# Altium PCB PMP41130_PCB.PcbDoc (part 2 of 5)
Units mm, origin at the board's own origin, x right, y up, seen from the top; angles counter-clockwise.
Board outline 74.13 x 200.91 mm, 6 copper layers (Top Layer, Layer 1, Inside Layer 1, Inside Layer 2, Layer 2, Bottom Layer), stack 2.208 mm thick; 356 components, 162 nets, 889 pads, 1511 vias.
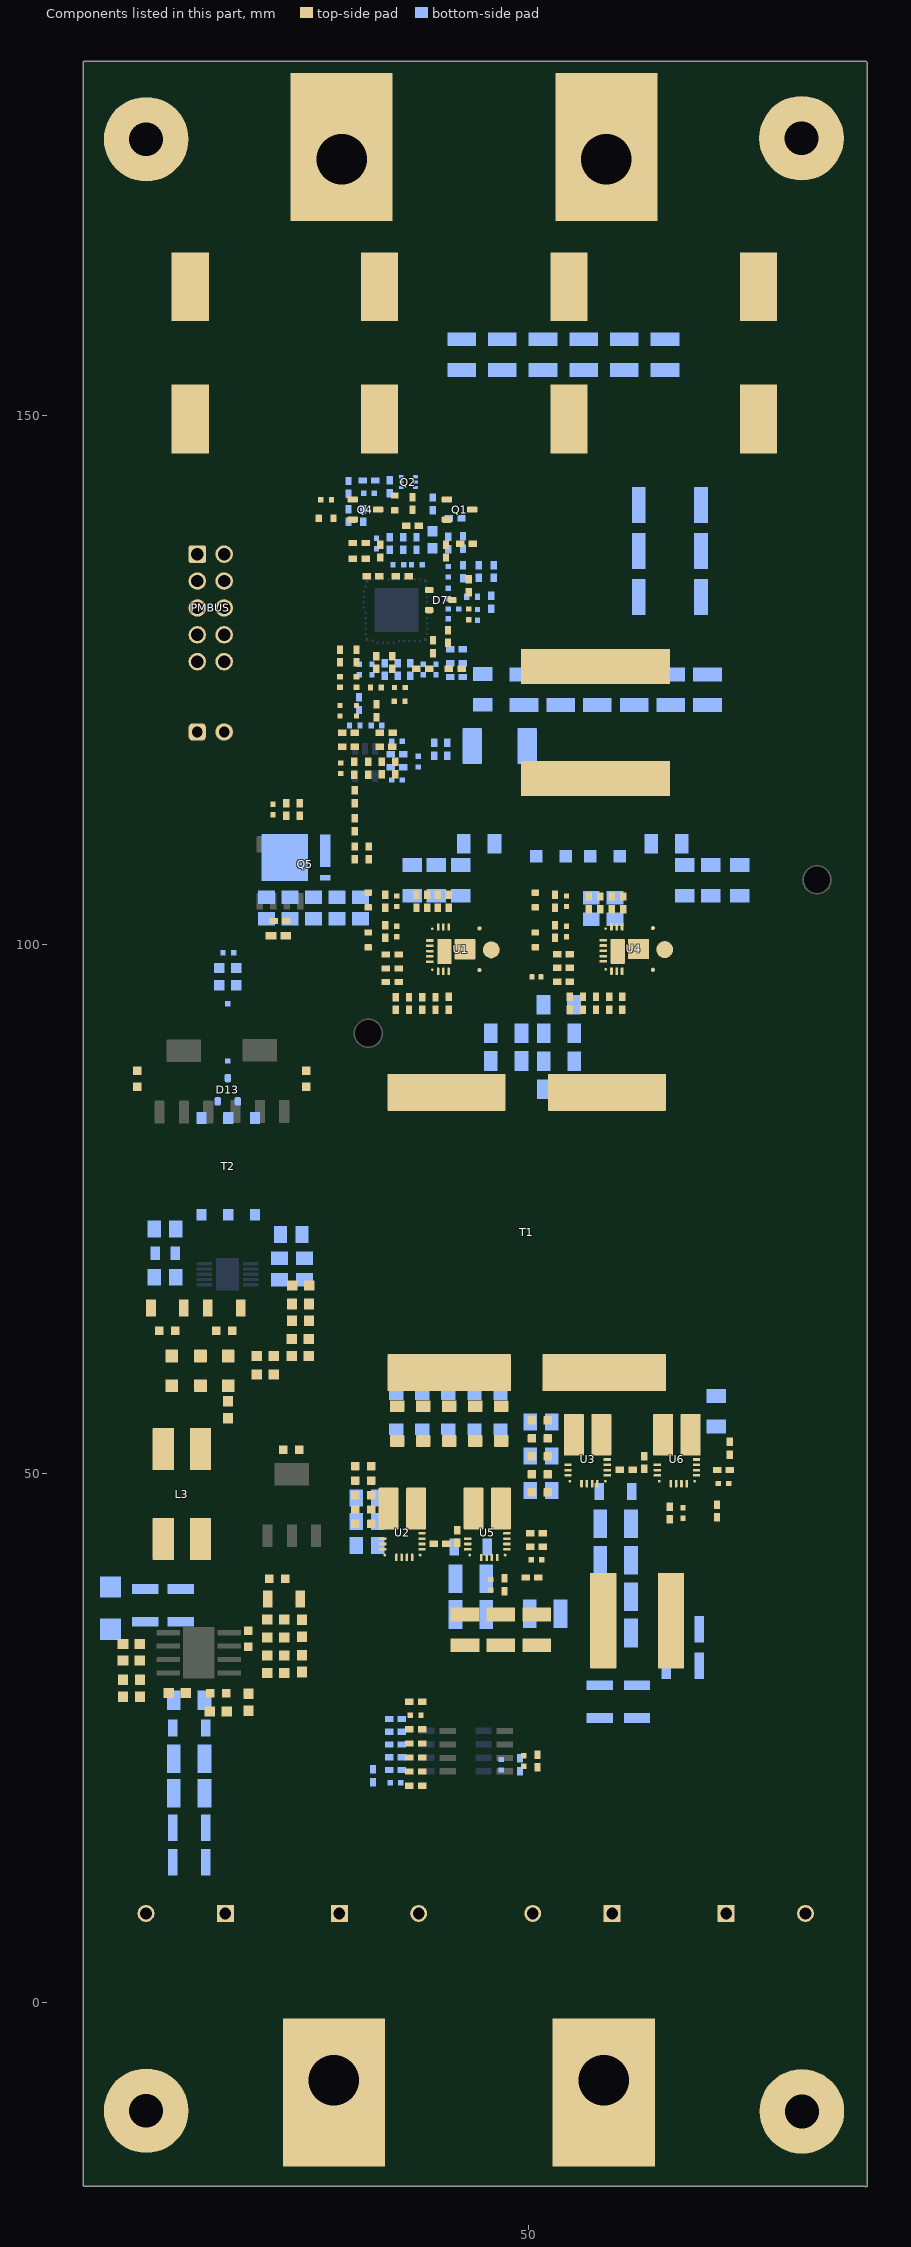
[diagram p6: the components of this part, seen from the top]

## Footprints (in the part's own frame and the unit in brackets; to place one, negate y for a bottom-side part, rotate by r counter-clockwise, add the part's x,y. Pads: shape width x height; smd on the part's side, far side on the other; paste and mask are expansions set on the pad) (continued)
TSW-102-07-G-S [mm] "Samtec 100mil, 1x2, 230 mil above insulator"
  rrect50% 1.65x1.65 hole 1.016: 1(-1.27,0)
  round 1.65 hole 1.016: 2(1.27,0)
  silkscreen extent -3.17,-1.27 2.54,1.27, body extent -2.54,-1.27 2.54,1.27, height 8.38
VBE0015A-MFG [mm]
  round 0.265 smd paste+0 mask-1000: 1(-1.675,2.875) 11(1.675,2.875)
  rrect40% 0.7x0.25 smd paste+0 mask-1000: 2(-1.85,2.325) 3(-1.85,1.825) 4(-1.85,1.325) 5(-1.85,0.825) 8(1.85,1.325) 9(1.85,1.825) 10(1.85,2.325)
  rrect11% 1.9x3.95 smd paste-1000 mask-1000: 6(-1.3,-1.525) 7(1.3,-1.525)
  rrect40% 0.25x0.7 smd paste+0 mask-1000: 12(0.575,3.1) 13(0.075,3.1) 14(-0.425,3.1) 15(-0.925,3.1)
  Top Layer region: -2.15,2.7 -2.169,2.704 -2.185,2.715 -2.196,2.731 -2.2,2.75 -2.2,2.75 -2.2,2.9 -2.193,2.925 -2.175,2.943 -2.15,2.95 -2.15,2.95 -1.85,2.95 -1.812,2.958 -1.779,2.979 -1.758,3.012 -1.75,3.05 -1.75,3.05 -1.75,3.4 -1.746,3.419 -1.735,3.435 -1.719,3.446 -1.7,3.45 -1.7,3.45 -1.55,3.45 -1.531,3.446 -1.515,3.435 -1.504,3.419 -1.5,3.4 -1.5,3.4 -1.5,2.75 -1.504,2.731 -1.515,2.715 -1.531,2.704 -1.55,2.7 -1.55,2.7
  Top Layer region: 2.15,2.7 2.169,2.704 2.185,2.715 2.196,2.731 2.2,2.75 2.2,2.75 2.2,2.9 2.193,2.925 2.175,2.943 2.15,2.95 2.15,2.95 1.85,2.95 1.812,2.958 1.779,2.979 1.758,3.012 1.75,3.05 1.75,3.05 1.75,3.4 1.746,3.419 1.735,3.435 1.719,3.446 1.7,3.45 1.7,3.45 1.55,3.45 1.531,3.446 1.515,3.435 1.504,3.419 1.5,3.4 1.5,3.4 1.5,2.75 1.504,2.731 1.515,2.715 1.531,2.704 1.55,2.7 1.55,2.7
  silkscreen extent -2.93,2.7 -2.68,2.95, body extent -2.35,-3.6 2.35,3.55, height 0.25
VBN0016A-MFG [mm]
  round 0.228 smd paste+0 mask+0: 1(-1.925,3.125) 11(1.925,3.125)
  rrect40% 0.7x0.25 smd paste+0 mask+0: 2(-2.1,2.575) 3(-2.1,2.075) 4(-2.1,1.575) 8(2.1,1.575) 9(2.1,2.075) 10(2.1,2.575)
  round 0.394 smd paste+0 mask+0: 5(-1.969,-1.335) 7(1.969,-1.335)
  rrect8% 2.35x1.33 smd paste-1000 mask+0: 6(-0.225,1.985)
  round 1.603 smd paste-1000 mask+0: 6(-0.059,-2.453)
  rrect5% 1.9x1.976 smd paste-1000 mask+0: 6(0,0.032)
  rrect40% 0.25x0.7 smd paste+0 mask+0: 12(0.825,3.35) 13(0.325,3.35) 14(-0.175,3.35) 15(-0.675,3.35) 16(-1.175,3.35)
  Top Layer region: -2.4,2.95 -2.419,2.954 -2.435,2.965 -2.446,2.981 -2.45,3 -2.45,3 -2.45,3.15 -2.443,3.175 -2.425,3.193 -2.4,3.2 -2.4,3.2 -2.05,3.2 -2.031,3.204 -2.015,3.215 -2.004,3.231 -2,3.25 -2,3.25 -2,3.65 -1.993,3.675 -1.975,3.693 -1.95,3.7 -1.95,3.7 -1.8,3.7 -1.781,3.696 -1.765,3.685 -1.754,3.669 -1.75,3.65 -1.75,3.65 -1.75,3 -1.754,2.981 -1.765,2.965 -1.781,2.954 -1.8,2.95 -1.8,2.95
  Top Layer region: 2.4,2.95 2.419,2.954 2.435,2.965 2.446,2.981 2.45,3 2.45,3 2.45,3.15 2.446,3.169 2.435,3.185 2.419,3.196 2.4,3.2 2.4,3.2 2.05,3.2 2.025,3.207 2.007,3.225 2,3.25 2,3.25 2,3.65 1.996,3.669 1.985,3.685 1.969,3.696 1.95,3.7 1.95,3.7 1.8,3.7 1.781,3.696 1.765,3.685 1.754,3.669 1.75,3.65 1.75,3.65 1.75,3 1.754,2.981 1.765,2.965 1.781,2.954 1.8,2.95 1.8,2.95
  Top Layer region: -0.55,-3.65 -0.554,-3.669 -0.565,-3.685 -0.581,-3.696 -0.6,-3.7 -0.6,-3.7 -0.75,-3.7 -0.775,-3.693 -0.793,-3.675 -0.8,-3.65 -0.8,-3.65 -0.8,-3.425 -0.804,-3.406 -0.815,-3.39 -0.831,-3.379 -0.85,-3.375 -0.85,-3.375 -0.9,-3.375 -0.925,-3.368 -0.943,-3.35 -0.95,-3.325 -0.95,-3.325 -0.95,-1.506 -0.943,-1.481 -0.925,-1.463 -0.9,-1.456 -0.9,-1.456 0.9,-1.456 0.919,-1.46 0.935,-1.471 0.946,-1.487 0.95,-1.506 0.95,-1.506 0.95,-3.325 0.943,-3.35 0.925,-3.368 0.9,-3.375 0.9,-3.375 0.5,-3.375 0.481,-3.379 0.465,-3.39 0.454,-3.406 0.45,-3.425 0.45,-3.425 0.45,-3.65 0.443,-3.675 0.425,-3.693 0.4,-3.7 0.4,-3.7 0.25,-3.7 0.231,-3.696 0.215,-3.685 0.204,-3.669 0.2,-3.65 0.2,-3.65 0.2,-3.425 0.196,-3.406 0.185,-3.39 0.169,-3.379 0.15,-3.375 0.15,-3.375 0,-3.375 -0.019,-3.379 -0.035,-3.39 -0.046,-3.406 -0.05,-3.425 -0.05,-3.425 -0.05,-3.65 -0.054,-3.669 -0.065,-3.685 -0.081,-3.696 -0.1,-3.7 -0.1,-3.7 -0.25,-3.7 -0.275,-3.693 -0.293,-3.675 -0.3,-3.65 -0.3,-3.65 -0.3,-3.425 -0.304,-3.406 -0.315,-3.39 -0.331,-3.379 -0.35,-3.375 -0.35,-3.375 -0.5,-3.375 -0.519,-3.379 -0.535,-3.39 -0.546,-3.406 -0.55,-3.425 -0.55,-3.425
  Top Layer region: -2.075,0.542 -2.1,0.535 -2.118,0.517 -2.125,0.492 -2.125,0.492 -2.125,0.338 -2.129,0.319 -2.14,0.303 -2.156,0.292 -2.175,0.288 -2.175,0.288 -2.4,0.288 -2.425,0.281 -2.443,0.263 -2.45,0.238 -2.45,0.238 -2.45,0.088 -2.443,0.063 -2.425,0.045 -2.4,0.038 -2.4,0.038 -2.175,0.038 -2.15,0.031 -2.132,0.013 -2.125,-0.012 -2.125,-0.012 -2.125,-0.162 -2.132,-0.187 -2.15,-0.205 -2.175,-0.212 -2.175,-0.212 -2.4,-0.212 -2.419,-0.216 -2.435,-0.227 -2.446,-0.243 -2.45,-0.262 -2.45,-0.262 -2.45,-0.412 -2.443,-0.437 -2.425,-0.455 -2.4,-0.462 -2.4,-0.462 -2.175,-0.462 -2.156,-0.466 -2.14,-0.477 -2.129,-0.493 -2.125,-0.512 -2.125,-0.512 -2.125,-0.662 -2.129,-0.681 -2.14,-0.697 -2.156,-0.708 -2.175,-0.712 -2.175,-0.712 -2.4,-0.712 -2.419,-0.716 -2.435,-0.727 -2.446,-0.743 -2.45,-0.762 -2.45,-0.762 -2.45,-0.912 -2.443,-0.937 -2.425,-0.955 -2.4,-0.962 -2.4,-0.962 -2.175,-0.962 -2.156,-0.966 -2.14,-0.977 -2.129,-0.993 -2.125,-1.012 -2.125,-1.012 -2.125,-1.162 -2.129,-1.181 -2.14,-1.197 -2.156,-1.208 -2.175,-1.212 -2.175,-1.212 -2.4,-1.212 -2.419,-1.216 -2.435,-1.227 -2.446,-1.243 -2.45,-1.262 -2.45,-1.262 -2.45,-1.412 -2.443,-1.437 -2.425,-1.455 -2.4,-1.462 -2.4,-1.462 -2.175,-1.462 -2.156,-1.466 -2.14,-1.477 -2.129,-1.493 -2.125,-1.512 -2.125,-1.512 -2.125,-1.662 -2.129,-1.681 -2.14,-1.697 -2.156,-1.708 -2.175,-1.712 -2.175,-1.712 -2.4,-1.712 -2.419,-1.716 -2.435,-1.727 -2.446,-1.743 -2.45,-1.762 -2.45,-1.762 -2.45,-1.912 -2.443,-1.937 -2.425,-1.955 -2.4,-1.962 -2.4,-1.962 -2.175,-1.962 -2.156,-1.966 -2.14,-1.977 -2.129,-1.993 -2.125,-2.012 -2.125,-2.012 -2.125,-2.162 -2.129,-2.181 -2.14,-2.197 -2.156,-2.208 -2.175,-2.212 -2.175,-2.212 -2.4,-2.212 -2.419,-2.216 -2.435,-2.227 -2.446,-2.243 -2.45,-2.262 -2.45,-2.262 -2.45,-2.412 -2.443,-2.437 -2.425,-2.455 -2.4,-2.462 -2.4,-2.462 -2.175,-2.462 -2.156,-2.466 -2.14,-2.477 -2.129,-2.493 -2.125,-2.512 -2.125,-2.512 -2.125,-2.662 -2.129,-2.681 -2.14,-2.697 -2.156,-2.708 -2.175,-2.712 -2.175,-2.712 -2.4,-2.712 -2.419,-2.716 -2.435,-2.727 -2.446,-2.743 -2.45,-2.762 -2.45,-2.762 -2.45,-2.912 -2.443,-2.937 -2.425,-2.955 -2.4,-2.962 -2.4,-2.962 -2.175,-2.962 -2.156,-2.966 -2.14,-2.977 -2.129,-2.993 -2.125,-3.012 -2.125,-3.012 -2.125,-3.166 -2.118,-3.191 -2.1,-3.209 -2.075,-3.216 -2.075,-3.216 -1.8,-3.216 -1.781,-3.212 -1.765,-3.201 -1.754,-3.185 -1.75,-3.166 -1.75,-3.166 -1.75,0.492 -1.754,0.511 -1.765,0.527 -1.781,0.538 -1.8,0.542 -1.8,0.542
  Top Layer region: 2.075,0.542 2.094,0.538 2.11,0.527 2.121,0.511 2.125,0.492 2.125,0.492 2.125,0.338 2.129,0.319 2.14,0.303 2.156,0.292 2.175,0.288 2.175,0.288 2.4,0.288 2.419,0.284 2.435,0.273 2.446,0.257 2.45,0.238 2.45,0.238 2.45,0.088 2.443,0.063 2.425,0.045 2.4,0.038 2.4,0.038 2.175,0.038 2.156,0.034 2.14,0.023 2.129,0.007 2.125,-0.012 2.125,-0.012 2.125,-0.162 2.132,-0.187 2.15,-0.205 2.175,-0.212 2.175,-0.212 2.4,-0.212 2.425,-0.219 2.443,-0.237 2.45,-0.262 2.45,-0.262 2.45,-0.412 2.446,-0.431 2.435,-0.447 2.419,-0.458 2.4,-0.462 2.4,-0.462 2.175,-0.462 2.156,-0.466 2.14,-0.477 2.129,-0.493 2.125,-0.512 2.125,-0.512 2.125,-0.662 2.129,-0.681 2.14,-0.697 2.156,-0.708 2.175,-0.712 2.175,-0.712 2.4,-0.712 2.419,-0.716 2.435,-0.727 2.446,-0.743 2.45,-0.762 2.45,-0.762 2.45,-0.912 2.446,-0.931 2.435,-0.947 2.419,-0.958 2.4,-0.962 2.4,-0.962 2.175,-0.962 2.156,-0.966 2.14,-0.977 2.129,-0.993 2.125,-1.012 2.125,-1.012 2.125,-1.162 2.129,-1.181 2.14,-1.197 2.156,-1.208 2.175,-1.212 2.175,-1.212 2.4,-1.212 2.419,-1.216 2.435,-1.227 2.446,-1.243 2.45,-1.262 2.45,-1.262 2.45,-1.412 2.446,-1.431 2.435,-1.447 2.419,-1.458 2.4,-1.462 2.4,-1.462 2.175,-1.462 2.156,-1.466 2.14,-1.477 2.129,-1.493 2.125,-1.512 2.125,-1.512 2.125,-1.662 2.129,-1.681 2.14,-1.697 2.156,-1.708 2.175,-1.712 2.175,-1.712 2.4,-1.712 2.419,-1.716 2.435,-1.727 2.446,-1.743 2.45,-1.762 2.45,-1.762 2.45,-1.912 2.446,-1.931 2.435,-1.947 2.419,-1.958 2.4,-1.962 2.4,-1.962 2.175,-1.962 2.156,-1.966 2.14,-1.977 2.129,-1.993 2.125,-2.012 2.125,-2.012 2.125,-2.162 2.129,-2.181 2.14,-2.197 2.156,-2.208 2.175,-2.212 2.175,-2.212 2.4,-2.212 2.419,-2.216 2.435,-2.227 2.446,-2.243 2.45,-2.262 2.45,-2.262 2.45,-2.412 2.446,-2.431 2.435,-2.447 2.419,-2.458 2.4,-2.462 2.4,-2.462 2.175,-2.462 2.156,-2.466 2.14,-2.477 2.129,-2.493 2.125,-2.512 2.125,-2.512 2.125,-2.662 2.129,-2.681 2.14,-2.697 2.156,-2.708 2.175,-2.712 2.175,-2.712 2.4,-2.712 2.419,-2.716 2.435,-2.727 2.446,-2.743 2.45,-2.762 2.45,-2.762 2.45,-2.912 2.446,-2.931 2.435,-2.947 2.419,-2.958 2.4,-2.962 2.4,-2.962 2.175,-2.962 2.156,-2.966 2.14,-2.977 2.129,-2.993 2.125,-3.012 2.125,-3.012 2.125,-3.166 2.121,-3.185 2.11,-3.201 2.094,-3.212 2.075,-3.216 2.075,-3.216 1.8,-3.216 1.775,-3.209 1.757,-3.191 1.75,-3.166 1.75,-3.166 1.75,0.492 1.754,0.511 1.765,0.527 1.781,0.538 1.8,0.542 1.8,0.542
  silkscreen extent -3.12,-3.88 2.63,3.88, body extent -2.55,-3.8 2.55,3.8, height 0.25
WCAP-ASLI_D16H17 [mm] "Aluminium Electrolytic V-Chip SMT Capacitors, 16x17mm"
  rect 6.5x3.5 smd: 1(6.25,0) 2(-6.25,0)
  silkscreen extent -8.65,-8.65 8.65,8.65, body extent -9.15,-8.5 9.15,8.5, height 17
WCAP-CSGP_0402_L1W0.5H0.5 [mm] "Ceramic Capacitors, body 1x0.5mm"
  rect 0.5x0.5 smd: 1(-0.5,0) 2(0.5,0)
  body extent -0.5,-0.25 0.5,0.25, height 0.5
WCAP-CSGP_0603_L1.6W0.8H0.8_Reflow [mm] "Ceramic Capacitors, body 1.6x0.8mm"
  rect 0.8x0.8 smd: 1(-0.75,0) 2(0.75,0)
  body extent -0.8,-0.4 0.8,0.4, height 0.8
WCAP-CSGP_0805_L2W1.25H1.25 [mm] "Ceramic Capacitors, body 2x1.25mm"
  rect 0.9x1.3 smd: 1(-0.95,0) 2(0.95,0)
  body extent -1,-0.63 1,0.63, height 1.25
WCAP-CSGP_1206_L3.2W1.6H1.6 [mm] "Ceramic Capacitors, body 3.2x1.6mm"
  rect 0.9x1.6 smd: 1(-1.55,0) 2(1.55,0)
  silkscreen extent -0.8,-0.95 0.8,0.95, body extent -1.6,-0.8 1.6,0.8, height 1.6
WCAP-CSGP_1206_L3.2W1.6H1.25 [mm] "Ceramic Capacitors, body 3.2x1.6mm"
  rect 0.9x1.6 smd: 1(-1.55,0) 2(1.55,0)
  silkscreen extent -0.8,-0.87 0.8,0.87, body extent -1.6,-0.8 1.6,0.8, height 1.25
WCAP-CSGP_1210_L3.2W2.5H2.5 [mm] "Ceramic Capacitors, body 3.2x2.5mm"
  rect 0.9x2.5 smd: 1(-1.55,0) 2(1.55,0)
  silkscreen extent -0.8,-1.4 0.8,1.4, body extent -1.6,-1.25 1.6,1.25, height 2.5
WCAP-CSRF_0402_L1W0.5H0.5 [mm] "Radio Frequency MLCC, body 1x0.5mm"
  rect 0.5x0.5 smd: 1(-0.5,0) 2(0.5,0)
  body extent -0.5,-0.25 0.5,0.25, height 0.5
WE-CBF_0402_L1W0.5H0.5_HS/WB [mm] "SMD EMI Suppression Ferrite  Bead, body 1.00x0.50mm"
  rect 0.5x0.6 smd: 1(-0.5,0) 2(0.5,0)
  body extent -0.5,-0.25 0.5,0.25, height 0.5
WE-TPC-LH [mm] "Wurth Elektronik recommended land pattern, 2009-01-15"
  rect 0.5x0.5 smd: 1(-2.7,0) 2(2.7,0)
  Top Layer region: 0.95,3.15 0.95,3.15 0.95,1.987 1.228,1.838 1.563,1.563 1.838,1.228 2.042,0.846 2.168,0.431 2.211,0 2.168,-0.431 2.042,-0.846 1.838,-1.228 1.563,-1.563 1.228,-1.838 0.95,-1.987 0.95,-3.15 3.15,-3.15 3.15,-3.15 3.15,3.15 0.95,3.15
  Top Layer region: -0.95,3.15 -0.95,3.15 -0.95,1.987 -1.228,1.838 -1.563,1.563 -1.838,1.228 -2.042,0.846 -2.168,0.431 -2.211,0 -2.168,-0.431 -2.042,-0.846 -1.838,-1.228 -1.563,-1.563 -1.228,-1.838 -0.95,-1.987 -0.95,-3.15 -3.15,-3.15 -3.15,-3.15 -3.15,3.15 -0.95,3.15
  silkscreen extent -3.4,-3.4 3.4,3.4, body extent -3.05,-3.05 3.05,3.05, height 3
WE-XHMI_1510_L16.4W15.4H10 [mm] "SMT Power Inductor, 2-Leads, body 16.4x15.4mm"
  rect 14.1x3.3 smd: 1(0,5.3) 2(0,-5.3)
  Top Layer keep-out region: -8.2,3.45 8.2,3.45 8.2,-3.45 -8.2,-3.45
  silkscreen extent -8.98,-7.85 8.35,7.85, body extent -8.2,-7.7 8.2,7.7, height 10
WEEE_Minimum [mm] "WEEElie bin"
  silkscreen extent -2.42,-4.38 2.52,2.65
Wurth_750316769 [mm] "SMD, 6-Leads, Body 7.14x6.73mm, Pitch 2.54mm"
  rrect10% 1.12x0.96 smd: 1(-4.57,2.54) 2(-4.57,0) 3(-4.57,-2.54) 4(4.57,-2.54) 5(4.57,0) 6(4.57,2.54)
  silkscreen extent -5,-3.36 3.57,3.36, body extent -5.02,-3.36 5.02,3.36, height 4.19
WURTH_61301021121 [mm] "Header, 2.54mm, 5x2, TH"
  rrect25% 1.65x1.65 hole 1.15: 1(-5.08,-1.27)
  round 1.65 hole 1.15: 2(-5.08,1.27) 3(-2.54,-1.27) 4(-2.54,1.27) 5(0,-1.27) 6(0,1.27) 7(2.54,-1.27) 8(2.54,1.27) 9(5.08,-1.27) 10(5.08,1.27)
  silkscreen extent -6.35,-2.9 6.35,2.54, body extent -6.35,-2.54 6.35,2.54, height 8.54

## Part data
C1 C7 C9 C20 C21 C22 C29 C32 C53 C54: library part CMP-0098402-1, "10 µF ±10% 100V Ceramic Capacitor X6S 1206 (3216 Metric)", Digikey Part Number=445-C3216X6S2A106K160ACCT-ND, Manufacturer=TDK, Mouser Part Number=810-C3216X6S2A106K16, Operating Temperature Range="-55°C to +105°C", TempCo=22%, Temperature Characteristic=X6S, Tolerance_%=10%, ValueDisplayed=10uF
C2 C63 C75 C76: library part CMP-0064928-2, "CAP, CERM, 0.47 uF, 25 V,+/- 10%, X5R, 0402", Cap_Case=0402, Manufacturer=MuRata, Supplier Part Number 1=490-14365-1-ND, TempCo=X5R, Tolerance_%=10%, Value1=Unknown, Value2=25V, ValueDisplayed=0.47uF
C3 C4: library part CMP-0064955-1, "CAP, CERM, 0.1 uF, 250 V,+/- 20%, X7T, 0805", Cap_Case=0805, Manufacturer=TDK, Supplier Part Number 1=445-6808-1-ND, TempCo=X7T, Tolerance_%=20%, Value1=Unknown, Value2=250V, ValueDisplayed=0.1uF
C5 C6: library part CMP-0009054-2, "CAP, CERM, 470 pF, 500 V, +/- 10%, X7R, 1206", Cap_Case=1206, Manufacturer=Vishay-Vitramon, Supplier Part Number 1=720-1029-1-ND, TempCo=X7R, Tolerance_%=10%, Value1=Unknown, Value2=500V, ValueDisplayed=470pF
C8 C74 C100 C147: library part CMP-0078625-1, "CAP, CERM, 1 µF, 25 V,+/- 20%, X5R, 0402", Cap_Case=0402, Manufacturer=MuRata, Supplier Part Number 1=490-10018-1-ND, TempCo=X5R, Tolerance_%=20%, Value2=25V, ValueDisplayed=1µF
C10 C11 C12 C13 C137 C138 C157 C158: library part CMP-0105033-1, "WCAP-CSGP Multilayer Ceramic Chip Capacitor, General Purpose, size 1210, X7R, 2.2µF, 100VDC", Capacitance Tolerance=+/-10%, Case/Size Code=1210, Insulation Resistance=0.05GOhm, Manufacturer="Wurth Elektronik", Operating Temperature Max=125°C, Operating Temperature Min=-55°C, Rated Voltage (DC)=100V
C14 C15 C16 C17 C18 C19 C141 C142 C143 C144 C145: library part CMP-0007891-2, "CAP, CERM, 1 uF, 100 V, +/- 10%, X7S, 0805", Cap_Case=0805, Manufacturer=TDK, Supplier Part Number 1=445-5205-1-ND, TempCo=X7S, Tolerance_%=10%, Value1="0.008255 ohm", Value2=100V, ValueDisplayed=1uF
C23 C24 C25 C26 C27 C28 C37 C38 C39 C40 C41 C42 C43 C45 C47 C48 C57 C58 C59 C60 C155 C156: library part CMP-0009135-2, "CAP, CERM, 4.7 uF, 100 V, +/- 10%, X7S, 1210", Cap_Case=1210, Manufacturer=TDK, Supplier Part Number 1=445-8912-1-ND, TempCo=X7S, Tolerance_%=10%, Value1=Unknown, Value2=100V, ValueDisplayed=4.7uF
C30 C31: library part CMP-0009030-2, "CAP, CERM, 100 pF, 1000 V, +/- 5%, C0G/NP0, 1206", Cap_Case=1206, Manufacturer=Vishay-Vitramon, Supplier Part Number 1=720-1011-1-ND, TempCo=C0G/NP0, Tolerance_%=5%, Value1=Unknown, Value2=1000V, ValueDisplayed=100pF
C33 C34 C35 C36: library part CMP-0009843-2, "CAP, AL, 470 uF, 100 V, +/- 20%, TH", Cap_Case=16x25mm, Manufacturer=Panasonic, Supplier Part Number 1=P5316-ND, Tolerance_%=20%, Value1=Unknown, Value2=100V, ValueDisplayed=470uF
C44 C127 C131: library part CMP-0115410-1, "WCAP-CSGP Multilayer Ceramic Chip Capacitor, General Purpose, size 0603, X7R, 2.2µF, 10VDC", Capacitance Tolerance=+/-10%, Case/Size Code=0603, Insulation Resistance=0.02GOhm, Manufacturer="Wurth Elektronik", Operating Temperature Max=125°C, Operating Temperature Min=-55°C, Rated Voltage (DC)=10V
C46 C128 C135: library part CMP-0108465-1, "WCAP-CSGP Multilayer Ceramic Chip Capacitor, General Purpose, size 1206, X7R, 22µF, 10VDC", Capacitance Tolerance=+/-10%, Case/Size Code=1206, Insulation Resistance=0.005GOhm, Manufacturer="Wurth Elektronik", Operating Temperature Max=125°C, Operating Temperature Min=-55°C, Rated Voltage (DC)=10V
C49 C50 C51 C52: library part CMP-0110669-1, "WCAP-ASLI Aluminum Electrolytic Capacitor, V-Chip, D16 x H17mm, 150uF, 100V", Capacitance Tolerance=+/-20%, Leakage Current=150uA, Manufacturer="Wurth Elektronik", Operating Temperature Max=105°C, Operating Temperature Min=-55°C, Rated Voltage (DC)=100V, Ripple Current=500mA
C55 C56 C99 C121: library part CMP-0081010-1, "CAP, CERM, 2.2 µF, 25 V,+/- 20%, X5R, 0402", Cap_Case=0402, Manufacturer=MuRata, Supplier Part Number 1=490-10457-1-ND, TempCo=X5R, Tolerance_%=20%, Value2=25V, ValueDisplayed=2.2µF
C61 C62: library part CMP-0009275-2, "CAP, CERM, 0.1 uF, 100 V, +/- 10%, X7R, 1210", Cap_Case=1210, Manufacturer=Vishay-Vitramon, Supplier Part Number 1=720-1082-1-ND, TempCo=X7R, Tolerance_%=10%, Value1=Unknown, Value2=100V, ValueDisplayed=0.1uF
C64 C65 C66 C67 C68 C69 C70 C71 C72 C73: library part CMP-0097294-1, "0.1 µF ±10% 100V Ceramic Capacitor X7R 0603 (1608 Metric)", Digikey Part Number=732-885012206120TR-ND, Manufacturer="Wurth Electronics", Mouser Part Number=710-885012206120, Operating Temperature Range="-55°C to +125°C", TempCo=15%, Temperature Characteristic=X7R, Tolerance_%=10%, ValueDisplayed=100nF
C77 C78: library part CMP-0053309-1, "WCAP-CSGP Multilayer Ceramic Chip Capacitor, General Purpose, size 0402, X7R, 100pF, 50VDC", Capacitance Tolerance=+/-10%, Case/Size Code=0402, Insulation Resistance=10GOhm, Manufacturer="Wurth Elektronik", Operating Temperature Max=125°C, Operating Temperature Min=-55°C, Rated Voltage (DC)=50V
C79 C80 C81 C86 C87 C91 C97 C98 C106 C107 C108 C109: library part CMP-0104156-1, "WCAP-CSGP Multilayer Ceramic Chip Capacitor, General Purpose, size 0402, NP0, 33pF, 50VDC", Capacitance Tolerance=+/-5%, Case/Size Code=0402, Insulation Resistance=10GOhm, Manufacturer="Wurth Elektronik", Operating Temperature Max=125°C, Operating Temperature Min=-55°C, Rated Voltage (DC)=50V
C82 C83 C93 C94: library part CMP-0006213-2, "CAP, CERM, 33 pF, 25 V, +/- 5%, C0G/NP0, 0402", Cap_Case=0402, Manufacturer="Wurth Elektronik", Supplier Part Number 1=710-885012005043, TempCo=C0G/NP0, Tolerance_%=5%, Value1=Unknown, Value2=25V, ValueDisplayed=33pF
C84 C85 C95 C96: library part CMP-0052531-1, "WCAP-CSGP Multilayer Ceramic Chip Capacitor, General Purpose, size 0402, X7R, 100nF, 16VDC", Capacitance Tolerance=+/-10%, Case/Size Code=0402, Insulation Resistance=5GOhm, Manufacturer="Wurth Elektronik", Operating Temperature Max=125°C, Operating Temperature Min=-55°C, Rated Voltage (DC)=16V
C88: library part CMP-0119248-1, "WCAP-CSGP Multilayer Ceramic Chip Capacitor, General Purpose, size 0402, X7R, 100nF, 10VDC", Capacitance Tolerance=+/-10%, Case/Size Code=0402, Insulation Resistance=5GOhm, Manufacturer="Wurth Elektronik", Operating Temperature Max=125°C, Operating Temperature Min=-55°C, Rated Voltage (DC)=10V
C89 C111 C119: library part CMP-0107736-1, "WCAP-CSGP Multilayer Ceramic Chip Capacitor, General Purpose, size 0402, NP0, 1nF, 50VDC", Capacitance Tolerance=+/-5%, Case/Size Code=0402, Insulation Resistance=10GOhm, Manufacturer="Wurth Elektronik", Operating Temperature Max=125°C, Operating Temperature Min=-55°C, Rated Voltage (DC)=50V
C90 C101 C103 C105: library part CMP-0119280-1, "WCAP-CSGP Multilayer Ceramic Chip Capacitor, General Purpose, size 0402, X7R, 10nF, 25VDC", Capacitance Tolerance=+/-10%, Case/Size Code=0402, Insulation Resistance=10GOhm, Manufacturer="Wurth Elektronik", Operating Temperature Max=125°C, Operating Temperature Min=-55°C, Rated Voltage (DC)=25V
C92 C113: library part CMP-0116016-1, "WCAP-CSRF Multilayer Ceramic Chip Capacitor, High Frequency, size 0402, NP0 Class I, 22pF, 50VDC", Capacitance Tolerance=+/-5%, Case/Size Code=0402, Insulation Resistance=10GOhm, Manufacturer="Wurth Elektronik", Operating Temperature Max=125°C, Operating Temperature Min=-55°C, Rated Voltage (DC)=50V
C102 C104: library part CMP-0006612-2, "CAP, CERM, 4.7 uF, 25 V, +/- 20%, X5R, 0402", Cap_Case=0402, Manufacturer=MuRata, TempCo=X5R, Tolerance_%=20%, Value1=Unknown, Value2=25V, ValueDisplayed=4.7uF
C110: library part CMP-0006852-4, "CAP, CERM, 0.01 uF, 200 V, +/- 10%, X7R, 0603", Cap_Case=0603, Manufacturer=Kemet, Supplier Part Number 1=399-5088-1-ND, TempCo=X7R, Tolerance_%=10%, Value1=Unknown, Value2=200V, ValueDisplayed=0.01uF
C112: library part CMP-0006684-2, "CAP, CERM, 0.022 uF, 50 V, +/- 10%, X7R, 0402", Cap_Case=0402, Manufacturer=MuRata, Supplier Part Number 1=490-3884-1-ND, TempCo=X7R, Tolerance_%=10%, Value1=Unknown, Value2=50V, ValueDisplayed=0.022uF
C114: library part CMP-0078224-1, "CAP, CERM, 0.01 µF, 50 V,+/- 10%, X8R, AEC-Q200 Grade 0, 0402", Cap_Case=0402, Manufacturer=TDK, Supplier Part Number 1=445-12303-1-ND, TempCo=X8R, Tolerance_%=10%, Value2=50V, ValueDisplayed=0.01µF
C115 C116 C117: library part CMP-0111322-1, "WCAP-CSGP Multilayer Ceramic Chip Capacitor, General Purpose, size 0402, NP0, 10pF, 50VDC", Capacitance Tolerance=+/-5%, Case/Size Code=0402, Insulation Resistance=10GOhm, Manufacturer="Wurth Elektronik", Operating Temperature Max=125°C, Operating Temperature Min=-55°C, Rated Voltage (DC)=50V
C118 C152 C154: library part CMP-0111809-1, "WCAP-CSGP Multilayer Ceramic Chip Capacitor, General Purpose, size 0402, X7R, 100nF, 50VDC", Capacitance Tolerance=+/-5%, Case/Size Code=0402, Insulation Resistance=0.5GOhm, Manufacturer="Wurth Elektronik", Operating Temperature Max=125°C, Operating Temperature Min=-55°C, Rated Voltage (DC)=50V
C120: library part CMP-0119274-1, "WCAP-CSGP Multilayer Ceramic Chip Capacitor, General Purpose, size 0402, X7R, 1nF, 25VDC", Capacitance Tolerance=+/-10%, Case/Size Code=0402, Insulation Resistance=10GOhm, Manufacturer="Wurth Elektronik", Operating Temperature Max=125°C, Operating Temperature Min=-55°C, Rated Voltage (DC)=25V
C122: library part CMP-0053546-1, "WCAP-CSGP Multilayer Ceramic Chip Capacitor, General Purpose, size 0402, X7R, 1.5nF, 50VDC", Capacitance Tolerance=+/-10%, Case/Size Code=0402, Insulation Resistance=10GOhm, Manufacturer="Wurth Elektronik", Operating Temperature Max=125°C, Operating Temperature Min=-55°C, Rated Voltage (DC)=50V
C123 C124 C160: library part CMP-0119652-1, "WCAP-CSGP Multilayer Ceramic Chip Capacitor, General Purpose, size 1206, X7R, 100nF, 100VDC", Capacitance Tolerance=+/-10%, Case/Size Code=1206, Insulation Resistance=1GOhm, Manufacturer="Wurth Elektronik", Operating Temperature Max=125°C, Operating Temperature Min=-55°C, Rated Voltage (DC)=100V
C125: library part CMP-0009043-2, "CAP, CERM, 0.01 uF, 1000 V, +/- 10%, X7R, 1206", Cap_Case=1206, Manufacturer=Vishay-Vitramon, Supplier Part Number 1=720-1022-1-ND, TempCo=X7R, Tolerance_%=10%, Value1=Unknown, Value2=1000V, ValueDisplayed=0.01uF
C126 C129 C136: library part CMP-0115435-1, "WCAP-CSGP Multilayer Ceramic Chip Capacitor, General Purpose, size 0603, X7R, 1µF, 16VDC", Capacitance Tolerance=+/-10%, Case/Size Code=0603, Insulation Resistance=0.1GOhm, Manufacturer="Wurth Elektronik", Operating Temperature Max=125°C, Operating Temperature Min=-55°C, Rated Voltage (DC)=16V
C130 C134: library part CMP-0111894-1, "WCAP-CSGP Multilayer Ceramic Chip Capacitor, General Purpose, size 0603, X7R, 2.2nF, 50VDC", Capacitance Tolerance=+/-10%, Case/Size Code=0603, Insulation Resistance=10GOhm, Manufacturer="Wurth Elektronik", Operating Temperature Max=125°C, Operating Temperature Min=-55°C, Rated Voltage (DC)=50V
C132: library part CMP-0006901-4, "CAP, CERM, 0.022 uF, 50 V, +/- 10%, X7R, 0603", Cap_Case=0603, Manufacturer=Kemet, Supplier Part Number 1=399-1280-1-ND, TempCo=X7R, Tolerance_%=10%, Value1=Unknown, Value2=50V, ValueDisplayed=0.022uF
C133: library part CMP-0081011-1, "CAP, CERM, 0.1 µF, 100 V,+/- 10%, X7R, AEC-Q200 Grade 1, 0603", Cap_Case=0603, Manufacturer="Taiyo Yuden", Supplier Part Number 1=587-6009-1-ND, TempCo=X7R, Tolerance_%=10%, Value2=100V, ValueDisplayed=0.1µF
C139: library part CMP-0006842-4, "CAP, CERM, 1000 pF, 50 V, +/- 5%, C0G/NP0, 0603", Cap_Case=0603, Manufacturer=Kemet, Supplier Part Number 1=317202, TempCo=C0G/NP0, Tolerance_%=5%, Value1=Unknown, Value2=50V, ValueDisplayed=1000pF
C140: library part CMP-0075366-3, "CAP, CERM, 2.2 µF, 25 V,+/- 10%, X7S, 0603", Cap_Case=0603, Manufacturer=MuRata, Supplier Part Number 1=490-12732-1-ND, TempCo=X7S, Tolerance_%=10%, Value2=25V, ValueDisplayed=2.2µF
C146: library part CMP-0006253-2, "CAP, CERM, 1 uF, 35 V, +/- 10%, JB, 0402", Cap_Case=0402, Manufacturer=TDK, Supplier Part Number 1=445-11014-1-ND, TempCo=JB, Tolerance_%=10%, Value1=Unknown, Value2=35V, ValueDisplayed=1uF
C148: library part CMP-0008303-3, "CAP, CERM, 10 uF, 25 V, +/- 20%, X5R, 0805", Cap_Case=0805, Manufacturer=MuRata, TempCo=X5R, Tolerance_%=20%, Value1=Unknown, Value2=25V, ValueDisplayed=10uF
C149: library part CMP-0008335-2, "CAP, CERM, 0.1 uF, 25 V, +/- 10%, X7R, 0805", Cap_Case=0805, Manufacturer=MuRata, Supplier Part Number 1=490-1673-1-ND, TempCo=X7R, Tolerance_%=10%, Value1=Unknown, Value2=25V, ValueDisplayed=0.1uF
C150 C151: library part CMP-0007357-5, "CAP, CERM, 4.7 uF, 35 V, +/- 10%, X5R, 0603", Cap_Case=0603, Manufacturer=MuRata, Supplier Part Number 1=490-7205-1-ND, TempCo=X5R, Tolerance_%=10%, Value1=Unknown, Value2=35V, ValueDisplayed=4.7uF
C153: library part CMP-0114900-1, "WCAP-CSGP Multilayer Ceramic Chip Capacitor, General Purpose, size 0402, NP0, 47pF, 50VDC", Capacitance Tolerance=+/-5%, Case/Size Code=0402, Insulation Resistance=10GOhm, Manufacturer="Wurth Elektronik", Operating Temperature Max=125°C, Operating Temperature Min=-55°C, Rated Voltage (DC)=50V
C159: library part CMP-0008711-2, "CAP, CERM, 1 uF, 100 V, +/- 20%, X7R, 1206", Cap_Case=1206, Manufacturer=TDK, Supplier Part Number 1=445-4468-1-ND, TempCo=X7R, Tolerance_%=20%, Value1=Unknown, Value2=100V, ValueDisplayed=1uF
Css1: library part CMP-0111941-1, "WCAP-CSGP Multilayer Ceramic Chip Capacitor, General Purpose, size 0805, X7R, 680nF, 10VDC", Capacitance Tolerance=+/-10%, Case/Size Code=0805, Insulation Resistance=0.7GOhm, Manufacturer="Wurth Elektronik", Operating Temperature Max=125°C, Operating Temperature Min=-55°C, Rated Voltage (DC)=10V
D1 D2 D9 D10 D12: library part CMP-0122261-1, "Diode 200 V 2A Surface Mount SOD-123W", Digikey Part Number=1727-7417-1-ND, Forward Current=2A, Manufacturer=Nexperia, Max Surge Forward Current=50A, Mouser Part Number=771-PNE20020ERX, Operating Temperature Range="to +175°C", Peak Reverse Current=0.01uA, ValueDisplayed=17pF
D3 D4 D5 D6 D8 D14: library part CMP-0122254-1, "Diode Schottky 40V 0.25A 2-Pin SOD-523 T/R", Digikey Part Number=SDM20U40-7DICT-ND, Forward Current=250mA, Manufacturer="Diodes Inc.", Max Surge Forward Current=1A, Mouser Part Number=621-SDM20U40, Operating Temperature Range="-65°C to +125°C", Peak Reverse Current=5uA, ValueDisplayed=50pF
D7: library part CMP-0076925-2, "Diode, Switching, 100 V, 0.215 A, SOT-23", Manufacturer=Nexperia, Value1=0.215A, Value2=1.25V
D11: library part CMP-0122570-1, "Diode TVS Single Uni-Dir 70V 400W Automotive 2-Pin SMA T/R", Breakdown Voltage=77.8V, Clamping Voltage=113V, Digikey Part Number=1SMA70AT3GOSCT-ND, Manufacturer=Littelfuse, Mouser Part Number=863-1SMA70AT3G, Operating Temperature Range="-65°C to +150°C", ValueDisplayed=190pF
D13: library part CMP-0077061-2, "Diode, Switching, 70 V, 0.25 A, AEC-Q101, SOT-23", Manufacturer=Vishay-Semiconductor, Value1=0.25A, Value2=1.25V
FB1 FB2 FB3 FB4 FB5 FB6: library part CMP-0066373-1, "WE-CBF SMT EMI Suppression Ferrite Bead, size 0402, 470Ohm, 0.62A", Case/Size Code=0402, DC Resistance Max=0.45Ohm, Manufacturer="Wurth Elektronik", Operating Temperature Max=125°C, Operating Temperature Min=-55°C, Rated Current=0.62A
H1 H2 H3 H4: library part CMP-0003617-1, "Machine Screw, Round, #4-40 x 1/4, Nylon, Philips panhead", Manufacturer="B&F Fastener Supply", Supplier Part Number 1=H542-ND
H5 H6 H7 H8: library part CMP-0003610-1, "Standoff, Hex, 0.5\"L #4-40 Nylon", Manufacturer=Keystone, Supplier Part Number 1=36-1902C-ND
J1: library part CMP-0075405-3, "Header, 100mil, 2x1, Gold, TH", Color=Black, Current_A=6.3A, Manufacturer=Samtec, Supplier Part Number 1=SAM1029-02-ND, Voltage_V=550V
L1: library part CMP-0124159-1, "1 µH Shielded Molded Inductor 48.2 A 1.61mOhm Max Nonstandard", Digikey Part Number=732-74439369010CT-ND, Manufacturer=Wurth, Mouser Part Number=710-74439369010, Operating Temperature Range="-40°C to +125°C", Self Resonant Frequency=40MHz, Test Frequency=100kHz, Tolerance_%=20%
L2: library part CMP-0099219-1, "WE-XHMI SMT Power Inductor, size 1510, 6.8uH, 15A, 4.1mOhm", Case/Size Code=1510, DC Resistance=4.1mOhm, Inductance=6.8uH, Manufacturer="Wurth Elektronik", Operating Temperature Max=125°C, Operating Temperature Min=-40°C, Performance Rated Current=25.3A, Rated Current=15A, Saturation Current=40.05A, Self Resonant Frequency=14MHz
L3: library part CMP-0122580-1, "Shielded Coupled Inductor 150uH 10% 100kHz 0.465Ohm 1.1A 12.3x12.3x6.2mm SMT AECQ200", Manufacturer=Coilcraft, Operating Temperature Range=to, Self Resonant Frequency=5.4MHz, Test Frequency=100kHz, Tolerance_%=10%
L4: library part CMP-0064419-2, "Inductor, Shielded Drum Core, Ferrite, 12 uH, 1.25 A, 0.06 ohm, SMD", Manufacturer="Wurth Elektronik", Supplier Part Number 1=732-1044-1-ND, Value1="0.06 ohm", Value2=1.25A, ValueDisplayed=12uH
Logo1: library part CMP-0074844-1
Logo2: library part CMP-0074838-1, "Texas Instrument Corporate Signature"
Logo3: library part CMP-0074847-1, "FCC_disclaimer"
Logo4: library part CMP-0074769-1
PMBUS: library part CMP-0054806-3, "Header, 2.54 mm, 5x2, Gold, TH", Current_A=3A, Manufacturer="Wurth Elektronik", Supplier Part Number 1=732-2672-ND, Voltage_V=250V
Q1: library part CMP-0000333-2, "Transistor, PNP, 150 V, 0.5 A, SOT-23", Manufacturer="ON Semiconductor", Supplier Part Number 1=MMBT5401LT1GOSCT-ND, Value1="0.5 A", Value2=240
Q2: library part CMP-0122249-1, "TRANS ARR 2NPN 50V 100MA SOT563", Collector Base Voltage=60V, Digikey Part Number=2156-EMX1DXV6T5-ND, Emitter Base Voltage=7V, Manufacturer="On Semiconductor", Mouser Part Number=863-EMX1DXV6T5, Operating Temperature Range="-55°C to +150°C", Power_W=500mW, Unity Gain Freq=180MHz
Q4: library part CMP-0000755-1, "MOSFET, N-CH, 50 V, 0.22 A, SOT-23", Alternate Manufacturer=None, Manufacturer="Fairchild Semiconductor", Supplier Part Number 1=BSS138CT-ND, Value2="1.7 nC"
Q5: library part CMP-0092601-1, "N-Channel 150 V 114A (Tc) 214W (Tc) Surface Mount, Wettable Flank PG-TSON-8-3", Digikey Part Number=448-BSC074N15NS5ATMA1CT-ND, Drain To Source Breakdown Voltage=150V, Input Capacitace At Vds="3100pF @ 75V", Manufacturer=Infineon, Mouser Part Number=726-BSC074N15NS5ATMA, Operating Temperature Range="-55°C to +175°C", Power_W=214W, Pulse Drain Current=456A, Typ Forward Diode Voltage=0.85V
R1 R2 R3 R4 R5 R6: library part CMP-0018106-2, "RES, 24.9, 1%, 0.25 W, 1206", Manufacturer="Yageo America", Power_W=250mW, Supplier Part Number 1=311-24.9FRCT-ND, TempCo="100 ppm/C", Tolerance_%=1%, Value2=0.25W, Value_Code=24R9, ValueDisplayed=24.9
R7 R8 R10: library part CMP-0015972-3, "RES, 4.7 k, 5%, 1 W, AEC-Q200 Grade 0, 2512", Manufacturer=Vishay-Dale, Power_W=1W, Supplier Part Number 1=541-4.7KXCT-ND, TempCo="200 ppm/C", Tolerance_%=5%, Value_Code=4k70, ValueDisplayed=4.7k
R9 R11 R14 R16 R17 R18 R19 R25 R28 R34 R35 R36 R37 R38 R85 R100: library part CMP-0027004-2, "RES, 0, 5%, 0.063 W, 0402", Manufacturer="Yageo America", Power_W=63mW, Supplier Part Number 1=311-0.0JRCT-ND, TempCo="200 ppm/C", Tolerance_%=5%, Value2=0.063W, Value_Code=0000, ValueDisplayed=0
R12 R13 R26 R27: library part CMP-0026926-3, "RES, 3.3, 5%, 0.063 W, AEC-Q200 Grade 0, 0402", Manufacturer=Vishay-Dale, Power_W=63mW, Supplier Part Number 1=541-3.3JCT-ND, TempCo="200 ppm/C", Tolerance_%=5%, Value2=0.063W, Value_Code=3R30, ValueDisplayed=3.3
R15 R33 R111 R134: library part CMP-0026658-1, "RES, 10.0 k, 1%, 0.1 W, 0402", Manufacturer=Panasonic, Power_W=100mW, Supplier Part Number 1=P10.0KLCT-ND, TempCo="100 ppm/C", Tolerance_%=1%, Value2=0.1W, Value_Code=10k0, ValueDisplayed=DNP
R20 R39: library part CMP-0026700-1, "RES, 4.70 k, 1%, 0.1 W, 0402", Manufacturer=Panasonic, Power_W=100mW, Supplier Part Number 1=P4.70KLCT-ND, TempCo="100 ppm/C", Tolerance_%=1%, Value2=0.1W, Value_Code=4k70, ValueDisplayed=4.70k
R21 R22 R23 R24: library part CMP-0018312-2, "RES, 46.4, 1%, 0.25 W, 1206", Manufacturer="Yageo America", Power_W=250mW, Supplier Part Number 1=311-46.4FRCT-ND, TempCo="100 ppm/C", Tolerance_%=1%, Value2=0.25W, Value_Code=46R4, ValueDisplayed=46.4
R29 R30 R40 R41 R44 R45 R62 R63 R65 R66 R71: library part CMP-0026749-1, "RES, 10.0, 1%, 0.063 W, 0402", Manufacturer="KOA Speer", Power_W=63mW, Supplier Part Number 1=660-RK73H1ETTP10R0F, TempCo="100 ppm/C", Tolerance_%=1%, Value2=0.063W, Value_Code=10R0, ValueDisplayed=10.0
R31 R32: library part CMP-0026194-2, "RES, 249, 1%, 0.063 W, AEC-Q200 Grade 0, 0402", Manufacturer=Vishay-Dale, Power_W=63mW, Supplier Part Number 1=541-249LCT-ND, TempCo="100 ppm/C", Tolerance_%=1%, Value2=0.063W, Value_Code=249R, ValueDisplayed=249
R42 R43 R56 R61 R64: library part CMP-0026763-1, "RES, 100, 1%, 0.063 W, AEC-Q200 Grade 0, 0402", Manufacturer="Stackpole Electronics Inc", Power_W=63mW, Supplier Part Number 1=RMCF0402JT100RCT-ND, TempCo="100 ppm/C", Tolerance_%=1%, Value2=0.063W, Value_Code=100R, ValueDisplayed=100
R46 R47 R57 R59: library part CMP-0078583-1, "RES, 15.0 k, 1%, 0.063 W, 0402", Manufacturer="Yageo America", Power_W=63mW, Supplier Part Number 1=311-15.0KLRCT-ND, TempCo="100 ppm/C", Tolerance_%=1%, Value2=0.063W, Value_Code=15k0, ValueDisplayed=15.0k
R48: library part CMP-0026735-1, "RES, 470 k, 1%, 0.0625 W, 0402", Manufacturer="Yageo America", Power_W=62.5mW, Supplier Part Number 1=311-470KLRCT-ND, TempCo="100 ppm/C", Tolerance_%=1%, Value2=0.0625W, Value_Code=470k
R49 R51 R54: library part CMP-0026717-1, "RES, 10.0, 1%, 0.063 W, 0402", Manufacturer=Rohm, Power_W=63mW, Supplier Part Number 1=RHM10.0LCT-ND, TempCo="100 ppm/C", Tolerance_%=1%, Value2=0.063W, Value_Code=10R0, ValueDisplayed=10.0
R50 R52 R53 R90 R92: library part CMP-0026657-1, "RES, 1.00 k, 1%, 0.1 W, 0402", Manufacturer=Panasonic, Power_W=100mW, Supplier Part Number 1=P1.00KLCT-ND, TempCo="100 ppm/C", Tolerance_%=1%, Value2=0.1W, Value_Code=1k00, ValueDisplayed=1.00k
R55: library part CMP-0027004-2, "RES, 0, 5%, 0.063 W, 0402", Manufacturer="Yageo America", PartNumber=RC0402JR-070RL, Power_W=63mW, Supplier Part Number 1=311-0.0JRCT-ND, TempCo="200 ppm/C", Tolerance_%=5%, Value2=0.063W, Value_Code=0000, ValueDisplayed=0
R58 R60 R68 R79: library part CMP-0026658-1, "RES, 10.0 k, 1%, 0.1 W, 0402", Manufacturer=Panasonic, Power_W=100mW, Supplier Part Number 1=P10.0KLCT-ND, TempCo="100 ppm/C", Tolerance_%=1%, Value2=0.1W, Value_Code=10k0, ValueDisplayed=10.0k
R67 R70: library part CMP-0026129-2, "RES, 1.00, 1%, 0.063 W, AEC-Q200 Grade 0, 0402", Manufacturer=Vishay-Dale, Power_W=63mW, Supplier Part Number 1=541-1.00LLCT-ND, TempCo="100 ppm/C", Tolerance_%=1%, Value2=0.063W, Value_Code=1R00, ValueDisplayed=1.00
R72 R95: library part CMP-0026681-1, "RES, 2.20 k, 1%, 0.1 W, 0402", Manufacturer=Panasonic, Power_W=100mW, Supplier Part Number 1=P2.20KLCT-ND, TempCo="100 ppm/C", Tolerance_%=1%, Value2=0.1W, Value_Code=2k20, ValueDisplayed=2.20k
R73 R74 R75: library part CMP-0026298-2, "RES, 33.2 k, 1%, 0.063 W, AEC-Q200 Grade 0, 0402", Manufacturer=Vishay-Dale, Power_W=63mW, Supplier Part Number 1=541-33.2KLCT-ND, TempCo="100 ppm/C", Tolerance_%=1%, Value2=0.063W, Value_Code=33k2, ValueDisplayed=33.2k
R76 R91: library part CMP-0065358-1, "RES, 20.0 k, .1%, .0625 W, 0402", Manufacturer="Yageo America", Power_W=62.5mW, Supplier Part Number 1=YAG1388CT-ND, TempCo="25 ppm/C", Tolerance_%=0.1%, Value1=.1%, Value2=.0625W, Value_Code=20k0, ValueDisplayed=20.0k
R77 R78 R94: library part CMP-0026668-1, "RES, 1.50 k, 1%, 0.1 W, AEC-Q200 Grade 0, 0402", Manufacturer=Panasonic, Power_W=100mW, Supplier Part Number 1=P1.50KLCT-ND, TempCo="100 ppm/C", Tolerance_%=1%, Value2=0.1W, Value_Code=1k50, ValueDisplayed=1.50k
R80: library part CMP-0026663-1, "RES, 120 k, 1%, 0.1 W, AEC-Q200 Grade 0, 0402", Manufacturer=Panasonic, Power_W=100mW, Supplier Part Number 1=P120KLCT-ND, TempCo="100 ppm/C", Tolerance_%=1%, Value2=0.1W, Value_Code=120k
R81 R82 R84 R86 R87 R88 R97 R108: library part CMP-0026879-3, "RES, 22 k, 5%, 0.063 W, AEC-Q200 Grade 0, 0402", Manufacturer=Vishay-Dale, Power_W=63mW, Supplier Part Number 1=541-22KJCT-ND, TempCo="200 ppm/C", Tolerance_%=5%, Value2=0.063W, Value_Code=22k0, ValueDisplayed=22k
R83: library part CMP-0026722-1, "RES, 100, 1%, 0.063 W, 0402", Manufacturer="Yageo America", Power_W=63mW, Supplier Part Number 1=311-100LRCT-ND, TempCo="100 ppm/C", Tolerance_%=1%, Value2=0.063W, Value_Code=100R, ValueDisplayed=100
R98: library part CMP-0027006-2, "RES, 51, 5%, 0.0625 W, 0402", Manufacturer="Yageo America", Power_W=62.5mW, Supplier Part Number 1=311-51JRCT-ND, TempCo="100 ppm/C", Tolerance_%=5%, Value2=0.0625W, Value_Code=51R0, ValueDisplayed=51
R99: library part CMP-0122260-1, "NTC Thermistor for Temperature Sensor, Automotive, 0402, 100kΩ, 3%, 0.032mA, 5V", B Tolerance=1%, Manufacturer=Murata, Max Current=0.032mA, Operating Temperature Range="-40°C to +125°C", Tolerance_%=3%
R101: library part CMP-0026816-1, "RES, 2.00 k, 0.1%, 0.063 W, 0402", Manufacturer="Susumu Co Ltd", Power_W=63mW, Supplier Part Number 1=RG10P2.0KBCT-ND, TempCo="25 ppm/C", Tolerance_%=0.1%, Value2=0.063W, Value_Code=2k00, ValueDisplayed=2.00k
R103: library part CMP-0081725-1, "RES, 39.0 k, 1%, 0.1 W, AEC-Q200 Grade 0, 0402", Manufacturer=Panasonic, Power_W=100mW, Supplier Part Number 1=P39.0KLCT-ND, TempCo="100 ppm/C", Tolerance_%=1%, Value2=0.1W, Value_Code=39k0, ValueDisplayed=39.0k
R104: library part CMP-0026721-1, "RES, 100 k, 1%, 0.0625 W, 0402", Manufacturer="Yageo America", Power_W=62.5mW, Supplier Part Number 1=311-100KLRCT-ND, TempCo="100 ppm/C", Tolerance_%=1%, Value2=0.0625W, Value_Code=100k
R106 R129: library part CMP-0026481-2, "RES, 5.62, 1%, 0.063 W, AEC-Q200 Grade 0, 0402", Manufacturer=Vishay-Dale, Power_W=63mW, Supplier Part Number 1=541-5.62LLCT-ND, TempCo="100 ppm/C", Tolerance_%=1%, Value2=0.063W, Value_Code=5R62, ValueDisplayed=5.62
R109 R110: library part CMP-0026749-1, "RES, 10.0, 1%, 0.063 W, 0402", Manufacturer="KOA Speer", PartNumber=RK73H1ETTP10R0F, Power_W=63mW, Supplier Part Number 1=660-RK73H1ETTP10R0F, TempCo="100 ppm/C", Tolerance_%=1%, Value2=0.063W, Value_Code=10R0, ValueDisplayed=10.0
R112 R120: library part CMP-0082530-1, "RES, 100 k, 5%, 0.1 W, 0603", Manufacturer=Vishay-Dale, Power_W=100mW, Supplier Part Number 1=541-3992-1-ND, TempCo="200 ppm/C", Tolerance_%=5%, Value2=0.1W, Value_Code=100k
R113: library part CMP-0023690-3, "RES, 120 k, 0.1%, 0.1 W, 0603", Manufacturer="Yageo America", Power_W=100mW, TempCo="25 ppm/C", Tolerance_%=0.1%, Value2=0.1W, Value_Code=120k
R114 R116: library part CMP-0023037-5, "RES, 33.0 k, 1%, 0.1 W, 0603", Manufacturer=Yageo, Power_W=100mW, Supplier Part Number 1=311-33.0KHRCT-ND, TempCo="100 ppm/C", Tolerance_%=1%, Value2=0.1W, Value_Code=33k0, ValueDisplayed=33.0k
R115: library part CMP-0023359-3, "RES, 10.0, 0.1%, 0.1 W, 0603", Manufacturer=Bourns, Power_W=100mW, Supplier Part Number 1=CRT0603-BY-10R0ELFCT-ND, TempCo="25 ppm/C", Tolerance_%=0.1%, Value2=0.1W, Value_Code=10R0, ValueDisplayed=10.0
R117: library part CMP-0024643-3, "RES, 12.0 k, 0.5%, 0.1 W, 0603", Manufacturer="Yageo America", Power_W=100mW, TempCo="50 ppm/C", Tolerance_%=0.5%, Value2=0.1W, Value_Code=12k0, ValueDisplayed=12.0k
R118: library part CMP-0023113-5, "RES, 43.0 k, 1%, 0.1 W, 0603", Manufacturer=Yageo, Power_W=100mW, Supplier Part Number 1=311-43.0KHRCT-ND, TempCo="100 ppm/C", Tolerance_%=1%, Value2=0.1W, Value_Code=43k0, ValueDisplayed=43.0k
R119: library part CMP-0022925-5, "RES, 22.0 k, 1%, 0.1 W, 0603", Manufacturer=Yageo, Power_W=100mW, Supplier Part Number 1=311-22.0KHRCT-ND, TempCo="100 ppm/C", Tolerance_%=1%, Value2=0.1W, Value_Code=22k0, ValueDisplayed=22.0k
R121: library part CMP-0023333-5, "RES, 9.10 k, 1%, 0.1 W, 0603", Manufacturer=Yageo, Power_W=100mW, Supplier Part Number 1=311-9.10KHRCT-ND, TempCo="100 ppm/C", Tolerance_%=1%, Value2=0.1W, Value_Code=9k10, ValueDisplayed=9.10k
R122 R128: library part CMP-0024300-2, "RES, 4.70 k, 0.1%, 0.1 W, 0603", Manufacturer="Yageo America", Power_W=100mW, TempCo="25 ppm/C", Tolerance_%=0.1%, Value2=0.1W, Value_Code=4k70, ValueDisplayed=4.70k
R123: library part CMP-0024263-2, "RES, 470, 0.1%, 0.1 W, 0603", Manufacturer="Yageo America", Power_W=100mW, TempCo="25 ppm/C", Tolerance_%=0.1%, Value2=0.1W, Value_Code=470R, ValueDisplayed=470
R124 R125: library part CMP-0022752-4, "RES, 110 k, 1%, 0.1 W, 0603", Manufacturer=Yageo, Power_W=100mW, Supplier Part Number 1=311-110KHRCT-ND, TempCo="100 ppm/C", Tolerance_%=1%, Value2=0.1W, Value_Code=110k
R126: library part CMP-0023863-3, "RES, 1.02 k, 0.1%, 0.1 W, 0603", Manufacturer="Yageo America", Power_W=100mW, TempCo="25 ppm/C", Tolerance_%=0.1%, Value2=0.1W, Value_Code=1k02, ValueDisplayed=1.02k
R127: library part CMP-0023592-3, "RES, 6.80 k, 0.1%, 0.1 W, 0603", Manufacturer="Susumu Co Ltd", Power_W=100mW, Supplier Part Number 1=RG16P6.8KBCT-ND, TempCo="25 ppm/C", Tolerance_%=0.1%, Value2=0.1W, Value_Code=6k80, ValueDisplayed=6.80k
R130: library part CMP-0020443-3, "RES, 0, 5%, 0.333 W, AEC-Q200 Grade 0, 0805", Manufacturer=Vishay-Dale, Power_W=333mW, Supplier Part Number 1=541-0.0TBCT-ND, TempCo="200 ppm/C", Tolerance_%=5%, Value2=0.333W, Value_Code=0000, ValueDisplayed=0
R131: library part CMP-0020429-1, "RES, 9.65 k, 0.1%, 0.125 W, 0805", Manufacturer="Yageo America", Power_W=125mW, TempCo="25 ppm/C", Tolerance_%=0.1%, Value2=0.125W, Value_Code=9k65, ValueDisplayed=9.65k
R132: library part CMP-0026747-1, "RES, 2.20, 1%, 0.2 W, 0402", Manufacturer=Vishay-Dale, Power_W=200mW, Supplier Part Number 1=RCS04022R20FKED-ND, TempCo="100 ppm/C", Tolerance_%=1%, Value2=0.2W, Value_Code=2R20, ValueDisplayed=2.20
R135 R136: library part CMP-0026918-5, "RES, 3.3 k, 5%, 0.063 W, AEC-Q200 Grade 0, 0402", Manufacturer=Vishay-Dale, Power_W=63mW, Supplier Part Number 1=541-3.3KJCT-ND, TempCo="200 ppm/C", Tolerance_%=5%, Value2=0.063W, Value_Code=3k30, ValueDisplayed=3.3k
Rlimit1: library part CMP-0019644-2, "RES, 18.2 k, 0.1%, 0.125 W, 0805", Manufacturer="Yageo America", Power_W=125mW, TempCo="25 ppm/C", Tolerance_%=0.1%, Value2=0.125W, Value_Code=18k2, ValueDisplayed=18.2k
RS1: library part CMP-0018759-2, "RES, 0, 5%, 0.25 W, 1206", Manufacturer="Yageo America", Power_W=250mW, Supplier Part Number 1=311-0.0ERCT-ND, TempCo="200 ppm/C", Tolerance_%=5%, Value2=0.25W, Value_Code=0000, ValueDisplayed=0
RSENSE1: library part CMP-0089827-1, "1 mOhms ±1% 5W Chip Resistor 2512 (6432 Metric) Automotive AEC-Q200, Current Sense, Moisture Resistant, Pulse Withstanding Metal Element", Digikey Part Number=541-3130-1-ND, Manufacturer=Vishay, Mouser Part Number=71-WSLF25121L000FEB, Operating Temperature Range="-65°C to +170°C", Power_W=5W, TempCo=170ppm/°C, Tolerance_%=1%
T1: library part CMP-0124000-1, "Transformer", Manufacturer=Cyntec, Operating Temperature Range=to, Voltage_Isolation_Vrms=1500VDC
T2: library part CMP-0067603-1, "Transformer, 350 uH, SMT", Manufacturer="Wurth Elektronik", ValueDisplayed=350µH
T3 T4 T5 T6: library part CMP-0055442-1, "Terminal 50A Lug", Manufacturer=Panduit, Supplier Part Number 1=CB35-36-CY-ND, Voltage_V=600V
